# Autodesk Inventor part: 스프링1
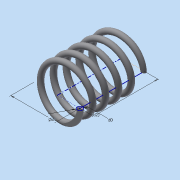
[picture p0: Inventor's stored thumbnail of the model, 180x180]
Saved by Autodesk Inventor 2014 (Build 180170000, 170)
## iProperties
Created: 2016-01
Part Number: 스프링1
Material: 강철, 탄소
Document SubType Name: Modeling
Designer: Administrator
Density: 7.87 g/cm^3
Appearance: 반연마
Mass: 6.46669 g
Surface Area: 16.7182 cm^2
Volume: 0.821689 cm^3
Author: Administrator
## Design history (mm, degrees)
sketch "스케치1"
  geometry: L1 (0, 0)-(0, 20.5); L2 (0, 20.5)-(8.5, 20.5); L3 (8.5, 20.5)-(8.5, 0); L4 (8.5, 0)-(0, 0); C1 r 1 at (8.5, 0)
  constraints: 8 end point, 2 parallel, 1 centre point, 1 coincident, 1 perpendicular, 1 vertical
  dimensions: "d0" = 2 diameter of C1; "d1" = 17 diameter of L3 L1; "d2" = 20.5 distance between parallel lines of L4 L2 (derived)
feature "코일1" pitch "d3" = 10; turns "d5" = 5; dims "d4" = 20.5 (= d2), "d6" = 0, angle "d7" = 90 deg, angle "d8" = 90 deg, "d9" = 0, "d10" = 0
node "작업 평면1"
sketch "스케치2"
  geometry: L1 (-9.5, 0)-(-7.5, 0) reference; L2 (-9.5, 0)-(-7.5, 0) reference; 1 further point
  constraints: 2 horizontal alignment
extrude "돌출1" cut sketch "스케치2" distance "d12" = 10; taper "d13" = 0 deg
node "작업 평면2"
sketch "스케치3"
  geometry: L1 (-7.5, 0)-(-9.5, 0) reference; 1 further point
  constraints: 1 horizontal alignment
extrude "돌출2" cut sketch "스케치3" distance "d15" = 10; taper "d16" = 0 deg
node "솔리드1"
node "절단 모서리 투영1"
node "절단 모서리 투영2"
node "절단 모서리 투영3"
other parameters: "d11" = 0, "d14" = 20.5 (= d2)
